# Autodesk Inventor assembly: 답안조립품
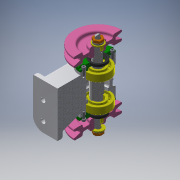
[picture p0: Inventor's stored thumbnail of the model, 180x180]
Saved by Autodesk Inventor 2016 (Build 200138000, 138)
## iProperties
Created: 2020-06
Part Number: 답안조립품
Material: 일반
Document SubType Name: Assembly
Designer: pc-04
Author: pc-04
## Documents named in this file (12)
- C:\Users\pc-04\Desktop\700606V1057\답안조립품.iam
- C:\Users\pc-04\Desktop\700606V1057\본체.ipt
- C:\Users\pc-04\Desktop\700606V1057\베어링 6204.ipt
- C:\Users\pc-04\Desktop\700606V1057\축.ipt
- C:\Users\pc-04\Desktop\700606V1057\커버.ipt
- C:\Users\pc-04\Desktop\700606V1057\오일 실 20 32 5.ipt
- C:\Users\pc-04\Desktop\700606V1057\키 5x5x12.ipt
- C:\Users\pc-04\Desktop\700606V1057\V-벨트풀리.ipt
- C:\Users\pc-04\Desktop\700606V1057\평면 와셔 10x21.ipt
- C:\Users\pc-04\Desktop\700606V1057\스프링 와셔 10.ipt
- C:\Users\pc-04\Desktop\700606V1057\너트 M10.ipt
- C:\Users\pc-04\Desktop\700606V1057\볼트 M4.ipt
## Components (2 placed, 1 different names)
1. V-벨트풀리:3
2. V-벨트풀리:4
